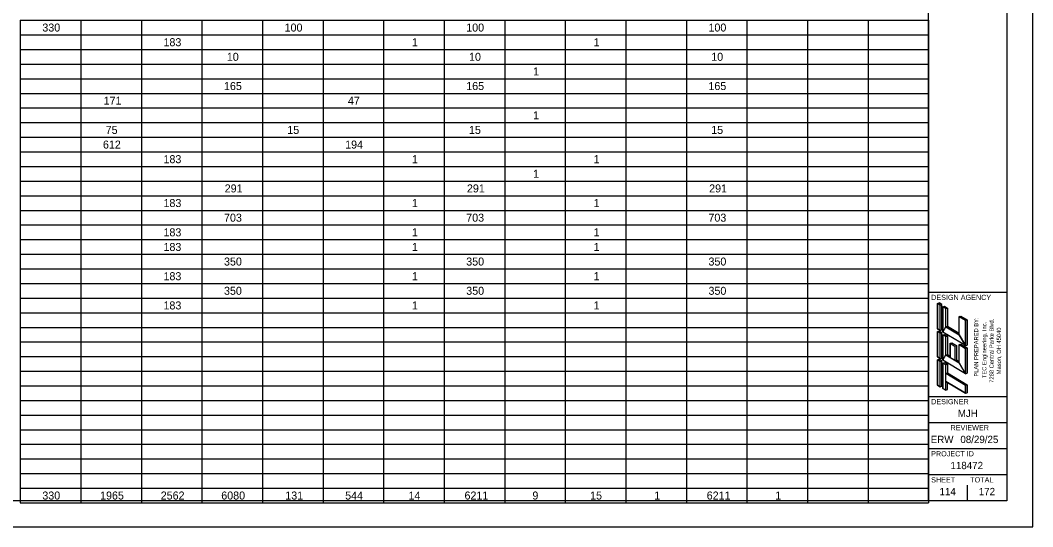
# Model space of a CAD drawing. Extents: x 0 to 34, y 0 to 22.
# Drawn here: x 14.57 to 34, y 0 to 9.72 of the extents above; entities that cross this region are included whole.
import ezdxf

# ---------------------------------------------------------------- set-up
doc = ezdxf.new("R2010")
doc.units = 0
for name, color, linetype in [('Default', 7, 'Continuous'), ('SH_Border', 7, 'Continuous'), ('SH_Cut_Line', 7, 'Continuous'), ('SH_Data', 7, 'Continuous'), ('SH_Text', 7, 'Continuous')]:
    doc.layers.add(name, color=color, linetype=linetype)

msp = doc.modelspace()

# ---------------------------------------------------------------- linework, layer by layer
at = {"layer": 'SH_Border'}
for p, q in [((32, 0.5), (32, 21.5)), ((32, 4.5), (33.5, 4.5)), ((32, 2.5), (33.5, 2.5)), ((32, 2), (33.5, 2)), ((32, 1.5), (33.5, 1.5)), ((32, 1), (33.5, 1))]:
    msp.add_line(p, q, dxfattribs=at)
msp.add_lwpolyline([(1.5, 21.5), (33.5, 21.5), (33.5, 0.5), (1.5, 0.5)], close=True, dxfattribs=at)
at = {"layer": 'SH_Cut_Line'}
msp.add_lwpolyline([(0, 0), (34, 0), (34, 22), (0, 22)], close=True, dxfattribs=at)
at = {"layer": 'SH_Data'}
for p, q in [((32.75, 3.5), (32.75, 3.5)), ((32.75, 0.5), (32.75, 0.8)), ((32.375, 0.675), (32.375, 0.675))]:
    msp.add_line(p, q, dxfattribs=at)
at = {"layer": 'SH_Text'}
for p, q in [((14.566, 9.717), (15.728, 9.717)), ((14.566, 9.717), (14.566, 9.156)), ((15.728, 9.717), (16.89, 9.717)), ((15.728, 9.717), (15.728, 9.156)), ((16.89, 9.717), (25.026, 9.717)), ((16.89, 9.717), (16.89, 9.156)), ((18.053, 9.717), (18.053, 9.156)), ((19.215, 9.717), (19.215, 9.156)), ((20.377, 9.717), (20.377, 9.156)), ((21.539, 9.717), (21.539, 9.156)), ((22.702, 9.717), (22.702, 9.156)), ((23.864, 9.717), (23.864, 9.156)), ((25.026, 9.717), (26.189, 9.717)), ((25.026, 9.717), (25.026, 9.156)), ((26.189, 9.717), (28.513, 9.717)), ((26.189, 9.717), (26.189, 9.156)), ((27.351, 9.717), (27.351, 9.156)), ((28.513, 9.717), (32, 9.717)), ((28.513, 9.717), (28.513, 9.156)), ((29.675, 9.717), (29.675, 9.156)), ((30.838, 9.717), (30.838, 9.156)), ((32, 9.717), (32, 9.156)), ((14.566, 9.436), (15.728, 9.436)), ((15.728, 9.436), (16.89, 9.436)), ((16.89, 9.436), (25.026, 9.436)), ((25.026, 9.436), (26.189, 9.436)), ((26.189, 9.436), (28.513, 9.436)), ((28.513, 9.436), (32, 9.436)), ((14.566, 9.156), (15.728, 9.156)), ((14.566, 9.156), (14.566, 8.314)), ((15.728, 9.156), (16.89, 9.156)), ((15.728, 9.156), (15.728, 8.314)), ((16.89, 9.156), (25.026, 9.156)), ((16.89, 9.156), (16.89, 8.314)), ((18.053, 9.156), (18.053, 8.314)), ((19.215, 9.156), (19.215, 8.314)), ((20.377, 9.156), (20.377, 8.314)), ((21.539, 9.156), (21.539, 8.314)), ((22.702, 9.156), (22.702, 8.314)), ((23.864, 9.156), (23.864, 8.314)), ((25.026, 9.156), (26.189, 9.156)), ((25.026, 9.156), (25.026, 8.314)), ((26.189, 9.156), (28.513, 9.156)), ((26.189, 9.156), (26.189, 8.314)), ((27.351, 9.156), (27.351, 8.314)), ((28.513, 9.156), (32, 9.156)), ((28.513, 9.156), (28.513, 8.314)), ((29.675, 9.156), (29.675, 8.314)), ((30.838, 9.156), (30.838, 8.314)), ((32, 9.156), (32, 8.314)), ((14.566, 8.875), (15.728, 8.875)), ((15.728, 8.875), (16.89, 8.875)), ((16.89, 8.875), (25.026, 8.875)), ((25.026, 8.875), (26.189, 8.875)), ((26.189, 8.875), (28.513, 8.875)), ((28.513, 8.875), (32, 8.875)), ((14.566, 8.595), (15.728, 8.595)), ((15.728, 8.595), (16.89, 8.595)), ((16.89, 8.595), (25.026, 8.595)), ((25.026, 8.595), (26.189, 8.595)), ((26.189, 8.595), (28.513, 8.595)), ((28.513, 8.595), (32, 8.595)), ((14.566, 8.314), (15.728, 8.314)), ((14.566, 8.314), (14.566, 7.753)), ((15.728, 8.314), (16.89, 8.314)), ((15.728, 8.314), (15.728, 7.753)), ((16.89, 8.314), (25.026, 8.314)), ((16.89, 8.314), (16.89, 7.753)), ((18.053, 8.314), (18.053, 7.753)), ((19.215, 8.314), (19.215, 7.753)), ((20.377, 8.314), (20.377, 7.753)), ((21.539, 8.314), (21.539, 7.753)), ((22.702, 8.314), (22.702, 7.753)), ((23.864, 8.314), (23.864, 7.753)), ((25.026, 8.314), (26.189, 8.314)), ((25.026, 8.314), (25.026, 7.753)), ((26.189, 8.314), (28.513, 8.314)), ((26.189, 8.314), (26.189, 7.753)), ((27.351, 8.314), (27.351, 7.753)), ((28.513, 8.314), (32, 8.314)), ((28.513, 8.314), (28.513, 7.753)), ((29.675, 8.314), (29.675, 7.753)), ((30.838, 8.314), (30.838, 7.753)), ((32, 8.314), (32, 7.753)), ((14.566, 8.034), (15.728, 8.034)), ((15.728, 8.034), (16.89, 8.034)), ((16.89, 8.034), (25.026, 8.034)), ((25.026, 8.034), (26.189, 8.034)), ((26.189, 8.034), (28.513, 8.034)), ((28.513, 8.034), (32, 8.034)), ((14.566, 7.753), (15.728, 7.753)), ((14.566, 7.753), (14.566, 6.911)), ((15.728, 7.753), (16.89, 7.753)), ((15.728, 7.753), (15.728, 6.911)), ((16.89, 7.753), (25.026, 7.753)), ((16.89, 7.753), (16.89, 6.911)), ((18.053, 7.753), (18.053, 6.911)), ((19.215, 7.753), (19.215, 6.911)), ((20.377, 7.753), (20.377, 6.911)), ((21.539, 7.753), (21.539, 6.911)), ((22.702, 7.753), (22.702, 6.911)), ((23.864, 7.753), (23.864, 6.911)), ((25.026, 7.753), (26.189, 7.753)), ((25.026, 7.753), (25.026, 6.911)), ((26.189, 7.753), (28.513, 7.753)), ((26.189, 7.753), (26.189, 6.911)), ((27.351, 7.753), (27.351, 6.911)), ((28.513, 7.753), (32, 7.753)), ((28.513, 7.753), (28.513, 6.911)), ((29.675, 7.753), (29.675, 6.911)), ((30.838, 7.753), (30.838, 6.911)), ((32, 7.753), (32, 6.911)), ((14.566, 7.472), (15.728, 7.472)), ((15.728, 7.472), (16.89, 7.472)), ((16.89, 7.472), (25.026, 7.472)), ((25.026, 7.472), (26.189, 7.472)), ((26.189, 7.472), (28.513, 7.472)), ((28.513, 7.472), (32, 7.472)), ((14.566, 7.192), (15.728, 7.192)), ((15.728, 7.192), (16.89, 7.192)), ((16.89, 7.192), (25.026, 7.192)), ((25.026, 7.192), (26.189, 7.192)), ((26.189, 7.192), (28.513, 7.192)), ((28.513, 7.192), (32, 7.192)), ((14.566, 6.911), (15.728, 6.911)), ((14.566, 6.911), (14.566, 6.35)), ((15.728, 6.911), (16.89, 6.911)), ((15.728, 6.911), (15.728, 6.35)), ((16.89, 6.911), (25.026, 6.911)), ((16.89, 6.911), (16.89, 6.35)), ((18.053, 6.911), (18.053, 6.35)), ((19.215, 6.911), (19.215, 6.35)), ((20.377, 6.911), (20.377, 6.35)), ((21.539, 6.911), (21.539, 6.35)), ((22.702, 6.911), (22.702, 6.35)), ((23.864, 6.911), (23.864, 6.35)), ((25.026, 6.911), (26.189, 6.911)), ((25.026, 6.911), (25.026, 6.35)), ((26.189, 6.911), (28.513, 6.911)), ((26.189, 6.911), (26.189, 6.35)), ((27.351, 6.911), (27.351, 6.35)), ((28.513, 6.911), (32, 6.911)), ((28.513, 6.911), (28.513, 6.35)), ((29.675, 6.911), (29.675, 6.35)), ((30.838, 6.911), (30.838, 6.35)), ((32, 6.911), (32, 6.35)), ((14.566, 6.631), (15.728, 6.631)), ((15.728, 6.631), (16.89, 6.631)), ((16.89, 6.631), (25.026, 6.631)), ((25.026, 6.631), (26.189, 6.631)), ((26.189, 6.631), (28.513, 6.631)), ((28.513, 6.631), (32, 6.631)), ((14.566, 6.35), (15.728, 6.35)), ((14.566, 6.35), (14.566, 0.459)), ((15.728, 6.35), (16.89, 6.35)), ((15.728, 6.35), (15.728, 0.459)), ((16.89, 6.35), (25.026, 6.35)), ((16.89, 6.35), (16.89, 0.459)), ((18.053, 6.35), (18.053, 0.459)), ((19.215, 6.35), (19.215, 0.459)), ((20.377, 6.35), (20.377, 0.459)), ((21.539, 6.35), (21.539, 0.459)), ((22.702, 6.35), (22.702, 0.459)), ((23.864, 6.35), (23.864, 0.459)), ((25.026, 6.35), (26.189, 6.35)), ((25.026, 6.35), (25.026, 0.459)), ((26.189, 6.35), (28.513, 6.35)), ((26.189, 6.35), (26.189, 0.459)), ((27.351, 6.35), (27.351, 0.459)), ((28.513, 6.35), (32, 6.35)), ((28.513, 6.35), (28.513, 0.459)), ((29.675, 6.35), (29.675, 0.459)), ((30.838, 6.35), (30.838, 0.459)), ((32, 6.35), (32, 0.459)), ((14.566, 6.07), (15.728, 6.07)), ((15.728, 6.07), (16.89, 6.07)), ((16.89, 6.07), (25.026, 6.07)), ((25.026, 6.07), (26.189, 6.07)), ((26.189, 6.07), (28.513, 6.07)), ((28.513, 6.07), (32, 6.07)), ((14.566, 5.789), (15.728, 5.789)), ((15.728, 5.789), (16.89, 5.789)), ((16.89, 5.789), (25.026, 5.789)), ((25.026, 5.789), (26.189, 5.789)), ((26.189, 5.789), (28.513, 5.789)), ((28.513, 5.789), (32, 5.789)), ((14.566, 5.509), (15.728, 5.509)), ((15.728, 5.509), (16.89, 5.509)), ((16.89, 5.509), (25.026, 5.509)), ((25.026, 5.509), (26.189, 5.509)), ((26.189, 5.509), (28.513, 5.509)), ((28.513, 5.509), (32, 5.509)), ((14.566, 5.228), (15.728, 5.228)), ((15.728, 5.228), (16.89, 5.228)), ((16.89, 5.228), (25.026, 5.228)), ((25.026, 5.228), (26.189, 5.228)), ((26.189, 5.228), (28.513, 5.228)), ((28.513, 5.228), (32, 5.228)), ((14.566, 4.947), (15.728, 4.947)), ((15.728, 4.947), (16.89, 4.947)), ((16.89, 4.947), (25.026, 4.947)), ((25.026, 4.947), (26.189, 4.947)), ((26.189, 4.947), (28.513, 4.947)), ((28.513, 4.947), (32, 4.947)), ((14.566, 4.667), (15.728, 4.667)), ((15.728, 4.667), (16.89, 4.667)), ((16.89, 4.667), (25.026, 4.667)), ((25.026, 4.667), (26.189, 4.667)), ((26.189, 4.667), (28.513, 4.667)), ((28.513, 4.667), (32, 4.667)), ((14.566, 4.386), (15.728, 4.386)), ((15.728, 4.386), (16.89, 4.386)), ((16.89, 4.386), (25.026, 4.386)), ((25.026, 4.386), (26.189, 4.386)), ((26.189, 4.386), (28.513, 4.386)), ((28.513, 4.386), (32, 4.386)), ((32.169, 4.285), (32.201, 4.294)), ((32.169, 3.799), (32.169, 4.285)), ((32.223, 4.253), (32.169, 4.285)), ((32.255, 4.261), (32.201, 4.294)), ((14.566, 4.106), (15.728, 4.106)), ((15.728, 4.106), (16.89, 4.106)), ((16.89, 4.106), (25.026, 4.106)), ((25.026, 4.106), (26.189, 4.106)), ((26.189, 4.106), (28.513, 4.106)), ((28.513, 4.106), (32, 4.106)), ((32.223, 4.253), (32.255, 4.261)), ((32.223, 3.767), (32.223, 4.253)), ((32.255, 3.775), (32.255, 4.261)), ((32.277, 4.221), (32.309, 4.229)), ((32.331, 4.188), (32.277, 4.221)), ((32.277, 3.735), (32.277, 4.221)), ((32.309, 4.229), (32.363, 4.196)), ((32.331, 4.188), (32.363, 4.196)), ((32.331, 3.837), (32.331, 4.188)), ((32.363, 4.196), (32.363, 3.845)), ((32.587, 4.034), (32.62, 4.042)), ((32.587, 3.683), (32.587, 4.034)), ((32.709, 3.961), (32.587, 4.034)), ((32.62, 4.042), (32.741, 3.97)), ((32.709, 3.961), (32.741, 3.97)), ((32.709, 3.475), (32.709, 3.961)), ((32.741, 3.97), (32.741, 3.484)), ((14.566, 3.825), (15.728, 3.825)), ((15.728, 3.825), (16.89, 3.825)), ((16.89, 3.825), (25.026, 3.825)), ((25.026, 3.825), (26.189, 3.825)), ((26.189, 3.825), (28.513, 3.825)), ((28.513, 3.825), (32, 3.825)), ((32.223, 3.767), (32.169, 3.799)), ((32.169, 3.745), (32.201, 3.754)), ((32.169, 3.259), (32.169, 3.745)), ((32.223, 3.713), (32.169, 3.745)), ((32.255, 3.722), (32.201, 3.754)), ((32.223, 3.767), (32.255, 3.775)), ((32.223, 3.713), (32.255, 3.722)), ((32.223, 3.227), (32.223, 3.713)), ((32.255, 3.236), (32.255, 3.722)), ((32.709, 3.475), (32.277, 3.735)), ((32.331, 3.837), (32.363, 3.845)), ((32.587, 3.683), (32.331, 3.837)), ((32.363, 3.845), (32.587, 3.711)), ((14.566, 3.545), (15.728, 3.545)), ((15.728, 3.545), (16.89, 3.545)), ((16.89, 3.545), (25.026, 3.545)), ((25.026, 3.545), (26.189, 3.545)), ((26.189, 3.545), (28.513, 3.545)), ((28.513, 3.545), (32, 3.545)), ((32.277, 3.681), (32.309, 3.689)), ((32.277, 3.195), (32.277, 3.681)), ((32.331, 3.648), (32.277, 3.681)), ((32.309, 3.689), (32.363, 3.656)), ((32.331, 3.648), (32.363, 3.656)), ((32.331, 3.297), (32.331, 3.648)), ((32.363, 3.656), (32.363, 3.305)), ((32.415, 3.519), (32.448, 3.527)), ((32.415, 3.519), (32.415, 3.247)), ((32.415, 3.519), (32.503, 3.466)), ((32.448, 3.527), (32.535, 3.474)), ((32.587, 3.494), (32.62, 3.502)), ((32.62, 3.502), (32.741, 3.43)), ((32.331, 3.297), (32.363, 3.305)), ((32.363, 3.305), (32.415, 3.274)), ((32.503, 3.466), (32.535, 3.474)), ((32.503, 3.466), (32.503, 3.194)), ((32.535, 3.474), (32.535, 3.202)), ((32.587, 3.143), (32.587, 3.494)), ((32.709, 3.421), (32.587, 3.494)), ((32.709, 3.475), (32.741, 3.484)), ((32.709, 3.421), (32.741, 3.43)), ((32.709, 2.935), (32.709, 3.421)), ((32.741, 3.43), (32.741, 2.944)), ((14.566, 3.264), (15.728, 3.264)), ((15.728, 3.264), (16.89, 3.264)), ((16.89, 3.264), (25.026, 3.264)), ((25.026, 3.264), (26.189, 3.264)), ((26.189, 3.264), (28.513, 3.264)), ((28.513, 3.264), (32, 3.264)), ((32.223, 3.227), (32.169, 3.259)), ((32.169, 3.205), (32.201, 3.215)), ((32.169, 2.719), (32.169, 3.205)), ((32.223, 3.173), (32.169, 3.205)), ((32.255, 3.181), (32.201, 3.215)), ((32.222, 3.173), (32.255, 3.181)), ((32.223, 3.227), (32.255, 3.236)), ((32.223, 2.687), (32.223, 3.173)), ((32.255, 2.695), (32.255, 3.181)), ((32.709, 2.935), (32.277, 3.195)), ((32.277, 3.141), (32.309, 3.151)), ((32.331, 3.108), (32.277, 3.141)), ((32.277, 2.655), (32.277, 3.141)), ((32.309, 3.151), (32.363, 3.116)), ((32.415, 3.247), (32.331, 3.297)), ((32.331, 3.108), (32.363, 3.116)), ((32.363, 3.116), (32.363, 2.952)), ((32.503, 3.194), (32.535, 3.202)), ((32.587, 3.143), (32.503, 3.194)), ((32.535, 3.202), (32.587, 3.171)), ((14.566, 2.984), (15.728, 2.984)), ((15.728, 2.984), (16.89, 2.984)), ((16.89, 2.984), (25.026, 2.984)), ((25.026, 2.984), (26.189, 2.984)), ((26.189, 2.984), (28.513, 2.984)), ((28.513, 2.984), (32, 2.984)), ((32.331, 2.944), (32.331, 3.108)), ((32.331, 2.944), (32.363, 2.952)), ((32.331, 2.944), (32.709, 2.717)), ((32.363, 2.952), (32.741, 2.725)), ((32.709, 2.935), (32.741, 2.944)), ((32.331, 2.787), (32.709, 2.56)), ((32.331, 2.622), (32.331, 2.787)), ((32.363, 2.63), (32.363, 2.767)), ((32.709, 2.717), (32.741, 2.725)), ((32.741, 2.725), (32.741, 2.568)), ((14.566, 2.703), (15.728, 2.703)), ((15.728, 2.703), (16.89, 2.703)), ((16.89, 2.703), (25.026, 2.703)), ((25.026, 2.703), (26.189, 2.703)), ((26.189, 2.703), (28.513, 2.703)), ((28.513, 2.703), (32, 2.703)), ((32.223, 2.687), (32.169, 2.719)), ((32.223, 2.687), (32.255, 2.695)), ((32.331, 2.622), (32.277, 2.655)), ((32.331, 2.622), (32.363, 2.63)), ((32.709, 2.56), (32.709, 2.717)), ((32.709, 2.56), (32.741, 2.568)), ((14.566, 2.422), (15.728, 2.422)), ((15.728, 2.422), (16.89, 2.422)), ((16.89, 2.422), (25.026, 2.422)), ((25.026, 2.422), (26.189, 2.422)), ((26.189, 2.422), (28.513, 2.422)), ((28.513, 2.422), (32, 2.422)), ((14.566, 2.142), (15.728, 2.142)), ((15.728, 2.142), (16.89, 2.142)), ((16.89, 2.142), (25.026, 2.142)), ((25.026, 2.142), (26.189, 2.142)), ((26.189, 2.142), (28.513, 2.142)), ((28.513, 2.142), (32, 2.142)), ((14.566, 1.861), (15.728, 1.861)), ((15.728, 1.861), (16.89, 1.861)), ((16.89, 1.861), (25.026, 1.861)), ((25.026, 1.861), (26.189, 1.861)), ((26.189, 1.861), (28.513, 1.861)), ((28.513, 1.861), (32, 1.861)), ((14.566, 1.581), (15.728, 1.581)), ((15.728, 1.581), (16.89, 1.581)), ((16.89, 1.581), (25.026, 1.581)), ((25.026, 1.581), (26.189, 1.581)), ((26.189, 1.581), (28.513, 1.581)), ((28.513, 1.581), (32, 1.581)), ((14.566, 1.3), (15.728, 1.3)), ((15.728, 1.3), (16.89, 1.3)), ((16.89, 1.3), (25.026, 1.3)), ((25.026, 1.3), (26.189, 1.3)), ((26.189, 1.3), (28.513, 1.3)), ((28.513, 1.3), (32, 1.3)), ((14.566, 1.02), (15.728, 1.02)), ((15.728, 1.02), (16.89, 1.02)), ((16.89, 1.02), (25.026, 1.02)), ((25.026, 1.02), (26.189, 1.02)), ((26.189, 1.02), (28.513, 1.02)), ((28.513, 1.02), (32, 1.02)), ((14.566, 0.739), (15.728, 0.739)), ((15.728, 0.739), (16.89, 0.739)), ((16.89, 0.739), (25.026, 0.739)), ((25.026, 0.739), (26.189, 0.739)), ((26.189, 0.739), (28.513, 0.739)), ((28.513, 0.739), (32, 0.739)), ((14.566, 0.459), (15.728, 0.459)), ((15.728, 0.459), (16.89, 0.459)), ((16.89, 0.459), (25.026, 0.459)), ((25.026, 0.459), (26.189, 0.459)), ((26.189, 0.459), (28.513, 0.459)), ((28.513, 0.459), (32, 0.459))]:
    msp.add_line(p, q, dxfattribs=at)
for points in [[(32.169, 3.799), (32.223, 3.767), (32.223, 4.253), (32.169, 4.285)], [(32.277, 3.735), (32.331, 3.837), (32.331, 4.188), (32.277, 4.221)], [(32.709, 3.475), (32.587, 3.683), (32.587, 4.034), (32.709, 3.961)], [(32.169, 3.259), (32.223, 3.227), (32.223, 3.713), (32.169, 3.745)], [(32.277, 3.735), (32.331, 3.837), (32.587, 3.683), (32.709, 3.475)], [(32.277, 3.195), (32.331, 3.297), (32.331, 3.648), (32.277, 3.681)], [(32.415, 3.247), (32.415, 3.519), (32.503, 3.466), (32.503, 3.194)], [(32.709, 2.935), (32.587, 3.143), (32.587, 3.494), (32.709, 3.421)], [(32.169, 2.719), (32.223, 2.687), (32.223, 3.173), (32.169, 3.205)], [(32.277, 3.195), (32.331, 3.297), (32.587, 3.143), (32.709, 2.935)], [(32.277, 2.655), (32.331, 2.622), (32.331, 3.108), (32.277, 3.141)], [(32.331, 2.787), (32.331, 2.944), (32.709, 2.717), (32.709, 2.56)]]:
    msp.add_lwpolyline(points, close=True, dxfattribs=at)

# ---------------------------------------------------------------- texts
at = {"layer": 'Default'}
for s, p in [('PLAN PREPARED BY:', (32.954, 2.88)), ('TEC Engineering, Inc.', (33.11, 2.851)), ('7288 Central Parke Blvd.', (33.25, 2.762)), ('Mason, OH 45040', (33.39, 2.925))]:
    msp.add_text(s, height=0.08, rotation=90, dxfattribs=at).set_placement(p)
at = {"layer": 'SH_Data'}
for s, height, p in [('DESIGN AGENCY', 0.1, (32.05, 4.35)), ('DESIGNER', 0.1, (32.05, 2.35)), ('MJH', 0.14, (32.561, 2.105)), ('REVIEWER', 0.1, (32.422, 1.85)), ('08/29/25', 0.14, (32.611, 1.605)), ('ERW', 0.14, (32.042, 1.605)), ('PROJECT ID', 0.1, (32.05, 1.35)), ('118472', 0.14, (32.421, 1.105)), ('SHEET', 0.1, (32.05, 0.85)), ('TOTAL', 0.1, (32.8, 0.85)), ('114', 0.14, (32.211, 0.605)), ('172', 0.14, (32.964, 0.605))]:
    msp.add_text(s, height=height, dxfattribs=at).set_placement(p)
at = {"layer": 'SH_Text'}
for s, height, p in [('330', 0.1536, (14.99, 9.5)), ('100', 0.1536, (19.64, 9.5)), ('100', 0.1536, (23.126, 9.5)), ('100', 0.1536, (27.776, 9.5)), ('183', 0.1536, (17.315, 9.219)), ('1', 0.154, (22.085, 9.219)), ('1', 0.154, (25.571, 9.219)), ('10', 0.1536, (18.531, 8.939)), ('10', 0.1536, (23.18, 8.939)), ('10', 0.1536, (27.829, 8.939)), ('1', 0.154, (24.409, 8.658)), ('165', 0.1536, (18.476, 8.378)), ('165', 0.1536, (23.126, 8.378)), ('165', 0.1536, (27.775, 8.378)), ('171', 0.1536, (16.166, 8.097)), ('47', 0.1536, (20.855, 8.097)), ('1', 0.154, (24.409, 7.816)), ('75', 0.1536, (16.206, 7.536)), ('15', 0.1536, (19.692, 7.536)), ('15', 0.1536, (23.179, 7.536)), ('15', 0.1536, (27.828, 7.536)), ('612', 0.1536, (16.153, 7.255)), ('194', 0.1536, (20.802, 7.255)), ('183', 0.1536, (17.315, 6.975)), ('1', 0.154, (22.085, 6.975)), ('1', 0.154, (25.571, 6.975)), ('1', 0.154, (24.409, 6.694)), ('291', 0.1536, (18.49, 6.414)), ('291', 0.1536, (23.14, 6.414)), ('291', 0.1536, (27.789, 6.414)), ('183', 0.1536, (17.315, 6.133)), ('1', 0.154, (22.085, 6.133)), ('1', 0.154, (25.571, 6.133)), ('703', 0.1536, (18.477, 5.853)), ('703', 0.1536, (23.126, 5.853)), ('703', 0.1536, (27.775, 5.853)), ('183', 0.1536, (17.315, 5.572)), ('1', 0.154, (22.085, 5.572)), ('1', 0.154, (25.571, 5.572)), ('183', 0.1536, (17.315, 5.291)), ('1', 0.154, (22.085, 5.291)), ('1', 0.154, (25.571, 5.291)), ('350', 0.1536, (18.477, 5.011)), ('350', 0.1536, (23.126, 5.011)), ('350', 0.1536, (27.776, 5.011)), ('183', 0.1536, (17.315, 4.73)), ('1', 0.154, (22.085, 4.73)), ('1', 0.154, (25.571, 4.73)), ('350', 0.1536, (18.477, 4.45)), ('350', 0.1536, (23.126, 4.45)), ('350', 0.1536, (27.776, 4.45)), ('183', 0.1536, (17.315, 4.169)), ('1', 0.154, (22.085, 4.169)), ('1', 0.154, (25.571, 4.169)), ('330', 0.1536, (14.99, 0.522)), ('1965', 0.1536, (16.098, 0.522)), ('2562', 0.1536, (17.262, 0.522)), ('6080', 0.1536, (18.424, 0.522)), ('131', 0.1536, (19.653, 0.522)), ('544', 0.1536, (20.802, 0.522)), ('14', 0.1536, (22.018, 0.522)), ('6211', 0.1536, (23.093, 0.522)), ('9', 0.154, (24.396, 0.522)), ('15', 0.1536, (25.504, 0.522)), ('1', 0.154, (26.734, 0.522)), ('6211', 0.1536, (27.742, 0.522)), ('1', 0.154, (29.058, 0.522))]:
    msp.add_text(s, height=height, dxfattribs=at).set_placement(p)

doc.saveas('drawing.dxf')
